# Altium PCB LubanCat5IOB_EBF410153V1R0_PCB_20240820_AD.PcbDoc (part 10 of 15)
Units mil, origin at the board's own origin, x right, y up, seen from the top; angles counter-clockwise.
Board outline 6811.02 x 4055.12 mil, 6 copper layers (TOP, GND02, ART03, ART04, PWR05, BOTTOM), stack 59.279 mil thick; 981 components, 783 nets, 3627 pads, 2669 vias.
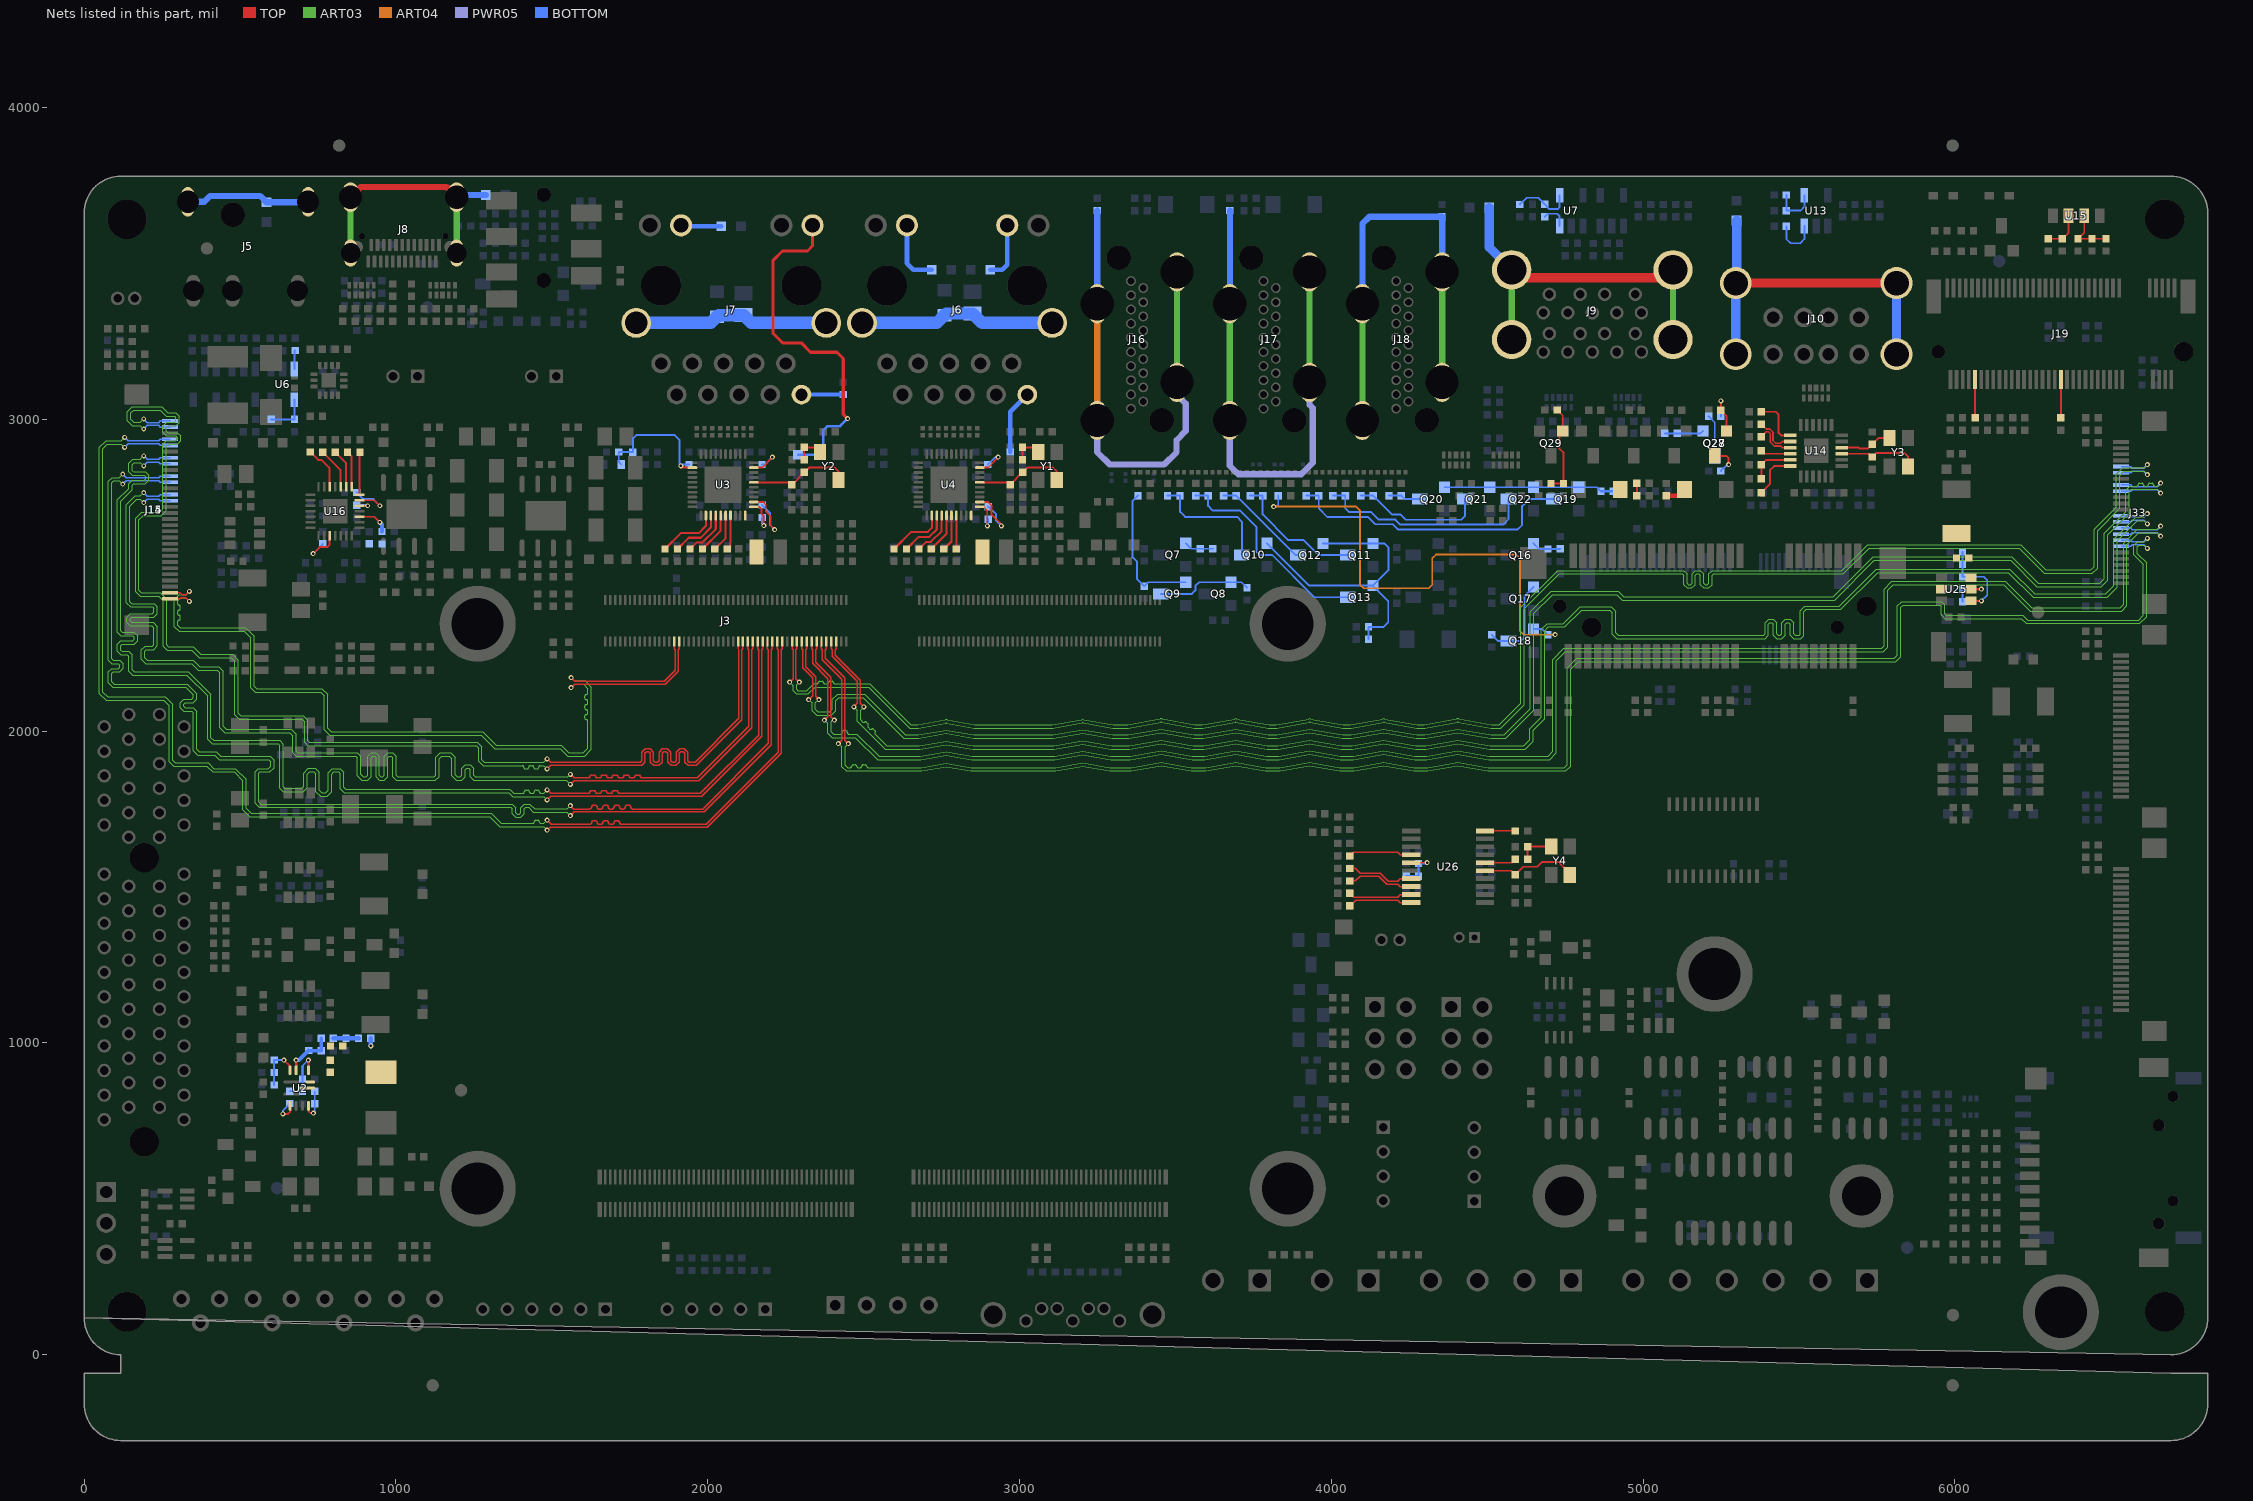
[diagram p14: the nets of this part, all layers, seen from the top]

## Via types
v1: diameter 16, hole 8, TOP to BOTTOM, 2357 vias
v2: diameter 14, hole 8, TOP to BOTTOM, 308 vias
v3: diameter 20, hole 10, TOP to BOTTOM, 4 vias

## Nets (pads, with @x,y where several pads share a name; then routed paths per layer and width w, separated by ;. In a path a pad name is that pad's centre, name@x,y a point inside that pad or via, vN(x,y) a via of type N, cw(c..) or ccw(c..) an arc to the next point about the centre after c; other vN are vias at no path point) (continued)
MIPI_DPHY0_TX_D3N: J3.31 J14.30 | length 2615.6
  TOP w4.5: J14.30@275.91,2424.15 307.43,2424.15 310.52,2427.25 326.5,2427.25 v1(337.83,2415.92) ; v1(1562,2139.17) 1573.33,2150.5 1864.5,2150.5 1905.25,2191.25 1905.25,2260.7 1908.37,2263.82 J3.31@1908.37,2286.88
  ART03 w4: v1(337.83,2415.92) 327.25,2426.5 309,2426.5 300,2417.5 300,2408.5 ccw(c304.5,2408.5) 304.5,2404 cw(c304.5,2399.5) 309,2399.5 309,2392.5 cw(c304.5,2392.5) 304.5,2388 ccw(c304.5,2383.5) 300,2383.5 300,2376.5 ccw(c304.5,2376.5) 304.5,2372 cw(c304.5,2367.5) 309,2367.5 309,2360.5 cw(c304.5,2360.5) 304.5,2356 ccw(c304.5,2351.5) 300,2351.5 300,2340 309,2331 518,2331 545.05,2303.95 545.05,2144 553.05,2136 763,2136 781.27,2117.73 781.27,2009.29 792.56,1998 1278,1998 1322,1954 1531,1954 1555,1930 1600.44,1930 1616,1945.56 1616,2031.61 ccw(c1610.5,2031.61) 1610.5,2037.11 cw(c1610.5,2042.61) 1605,2042.61 1605,2047.61 cw(c1610.5,2047.61) 1610.5,2053.11 ccw(c1610.5,2058.61) 1616,2058.61 1616,2063.61 ccw(c1610.5,2063.61) 1610.5,2069.11 cw(c1610.5,2074.61) 1605,2074.61 1605,2079.61 cw(c1610.5,2079.61) 1610.5,2085.11 ccw(c1610.5,2090.61) 1616,2090.61 1616,2095.61 ccw(c1610.5,2095.61) 1610.5,2101.11 cw(c1610.5,2106.61) 1605,2106.61 1605,2111.61 cw(c1610.5,2111.61) 1610.5,2117.11 ccw(c1610.5,2122.61) 1616,2122.61 1616,2136.44 1602.69,2149.75 1572.58,2149.75 v1(1562,2139.17)
MIPI_DPHY0_TX_D3P: J3.29 J14.29 | length 2616.2
  TOP w4.5: J14.29@275.91,2443.85 307.43,2443.85 314.52,2436.75 326.5,2436.75 v1(337.83,2448.08) ; v1(1562,2171.33) 1573.33,2160 1860.56,2160 1895.75,2195.18 1895.75,2260.7 1892.62,2263.82 J3.29@1892.62,2286.88
  ART03 w4: v1(337.83,2448.08) 327.25,2437.5 304.44,2437.5 289,2422.06 289,2335.44 304.44,2320 513.44,2320 534.05,2299.39 534.05,2139.44 548.49,2125 758.44,2125 770.27,2113.17 770.27,2004.73 788,1987 1273.44,1987 1317.44,1943 1526.44,1943 1550.44,1919 1605,1919 1627,1941 1627,2141 1607.25,2160.75 1572.58,2160.75 v1(1562,2171.33)
MIPI_DPHY1_RX_CLKN: J3.87 J33.10 | length 5558
  TOP w4.5: J3.87@2349.32,2286.88 2349.32,2263.82 2346.19,2260.7 2346.19,2220.81 2395,2172 2395,2046.33 v1(2406.33,2035)
  ART03 w4: v1(2406.33,2035) 2400,2035 2395.75,2030.75 2395.75,1998 2403.75,1990 2425.64,1990 ccw(c2425.64,1996) 2431.64,1996 cw(c2437.64,1996) 2437.64,2002 2441.64,2002 cw(c2441.64,1996) 2447.64,1996 ccw(c2453.64,1996) 2453.64,1990 2478.56,1990 2549.56,1919 2681.91,1919 2765.07,1933.44 2848.24,1919 3112.75,1919 3202.96,1934.66 3293.16,1919 3354.75,1919 3454.61,1936.34 3554.46,1919 3593.75,1919 3693.11,1936.25 3792.46,1919 3831.75,1919 3931.14,1936.26 4030.52,1919 4069.81,1919 4169.1,1936.24 4268.38,1919 4305.75,1919 4406.13,1936.43 4506.5,1919 4695.44,1919 4711,1934.56 4711,2229.56 4746.44,2265 5766,2265 5774,2273 5774,2455.56 5798.44,2480 6162,2480 6245.99,2396.01 6530.45,2396.01 6541,2406.56 6541,2603 6585.15,2647.15 6649.42,2647.15 v1(6660,2657.73)
  BOTTOM w4.5: J33.10@6533.11,2651.49 6564.63,2651.49 6569.73,2646.4 6648.67,2646.4 v1(6660,2657.73)
MIPI_DPHY1_RX_CLKP: J3.85 J33.9 | length 5558.6
  TOP w4.5: J3.85@2333.57,2286.88 2333.57,2263.82 2336.69,2260.7 2336.69,2216.87 2385.5,2168.07 2385.5,2046.33 v1(2374.17,2035)
  ART03 w4: v1(2374.17,2035) 2384.75,2024.42 2384.75,1993.44 2399.19,1979 2474,1979 2545,1908 2682.85,1908 2765.07,1922.28 2847.3,1908 3113.7,1908 3202.96,1923.5 3292.22,1908 3355.7,1908 3454.61,1925.17 3553.51,1908 3594.7,1908 3693.11,1925.09 3791.52,1908 3832.7,1908 3931.14,1925.09 4029.57,1908 4070.76,1908 4169.1,1925.07 4267.43,1908 4306.7,1908 4406.13,1925.26 4505.55,1908 4700,1908 4722,1930 4722,2225 4751,2254 5770.56,2254 5785,2268.44 5785,2451 5803,2469 6157.44,2469 6241.43,2385.01 6535.01,2385.01 6552,2402 6552,2598.44 6589.71,2636.15 6649.42,2636.15 v1(6660,2625.57)
  BOTTOM w4.5: J33.9@6533.11,2631.81 6564.63,2631.81 6569.73,2636.9 6648.67,2636.9 v1(6660,2625.57)
MIPI_DPHY1_RX_D0N: J3.95 J33.12 | length 5560.8
  TOP w4.5: J3.95@2412.31,2286.88 2412.31,2263.82 2409.18,2260.7 2409.18,2243.94 2489.5,2163.62 2489.5,2089.33 v1(2500.83,2078)
  ART03 w4: v1(2500.83,2078) 2490.25,2067.42 2490.25,2036.75 2497.85,2029.15 ccw(c2500.6,2031.9) 2503.35,2029.15 cw(c2506.1,2026.4) 2508.85,2029.15 2514.67,2023.33 cw(c2511.92,2020.58) 2514.67,2017.83 ccw(c2517.42,2015.08) 2514.67,2012.33 2520.48,2006.52 ccw(c2523.23,2009.27) 2525.98,2006.52 cw(c2528.73,2003.77) 2531.48,2006.52 2537.3,2000.7 cw(c2534.55,1997.95) 2537.3,1995.2 ccw(c2540.05,1992.45) 2537.3,1989.7 2574,1953 2678.97,1953 2765.07,1967.95 2851.17,1953 3109.82,1953 3202.96,1969.17 3296.09,1953 3351.82,1953 3454.61,1970.85 3557.39,1953 3590.82,1953 3693.11,1970.76 3795.39,1953 3828.82,1953 3931.14,1970.77 4033.45,1953 4066.88,1953 4169.1,1970.75 4271.31,1953 4302.82,1953 4406.13,1970.94 4509.43,1953 4617.44,1953 4637,1972.56 4637,2007.56 4674,2044.56 4674,2327 4692,2345 4744.44,2345 4798.44,2399 4897.56,2399 4912,2384.56 4912,2315 4920,2307 5386.63,2307 5391.31,2311.69 5391.31,2346.87 5402.44,2358 5418.19,2358 5429.31,2346.87 5429.31,2311.69 5434,2307 5440.63,2307 5445.31,2311.69 5445.31,2346.87 5456.44,2358 5472.19,2358 5483.31,2346.87 5483.31,2311.69 5488,2307 5501,2307 5505,2311 5505,2386.56 5519.44,2401 5629.44,2401 5747.81,2519.37 6176.63,2519.37 6255.63,2440.37 6483.81,2440.37 6510,2466.56 6510,2615.56 6580.44,2686 6606.58,2686 v1(6617.69,2697.1)
  BOTTOM w4.5: J33.12@6533.11,2690.86 6564.63,2690.86 6569.73,2685.77 6606.35,2685.77 v1(6617.69,2697.1)
MIPI_DPHY1_RX_D0P: J3.93 J33.11 | length 5560.6
  TOP w4.5: J3.93@2396.56,2286.88 2396.56,2263.82 2399.68,2260.7 2399.68,2240 2480,2159.68 2480,2089.33 v1(2468.67,2078)
  ART03 w4: v1(2468.67,2078) 2479.25,2067.42 2479.25,2032.19 2569.44,1942 2679.92,1942 2765.07,1956.79 2850.23,1942 3110.77,1942 3202.96,1958.01 3295.15,1942 3352.77,1942 3454.61,1959.68 3556.45,1942 3591.77,1942 3693.11,1959.6 3794.45,1942 3829.77,1942 3931.14,1959.6 4032.5,1942 4067.82,1942 4169.1,1959.58 4270.36,1942 4303.77,1942 4406.13,1959.77 4508.48,1942 4622,1942 4648,1968 4648,2003 4685,2040 4685,2322.44 4696.56,2334 4749,2334 4803,2388 4893,2388 4901,2380 4901,2310.44 4915.44,2296 5391.19,2296 5402.31,2307.13 5402.31,2342.31 5407,2347 5413.63,2347 5418.31,2342.31 5418.31,2307.13 5429.44,2296 5445.19,2296 5456.31,2307.13 5456.31,2342.31 5461,2347 5467.63,2347 5472.31,2342.31 5472.31,2307.13 5483.44,2296 5505.56,2296 5516,2306.44 5516,2382 5524,2390 5634,2390 5752.37,2508.37 6172.07,2508.37 6251.07,2429.37 6488.37,2429.37 6521,2462 6521,2611 6585,2675 6607.63,2675 v1(6617.69,2664.94)
  BOTTOM w4.5: J33.11@6533.11,2671.18 6564.63,2671.18 6569.73,2676.27 6606.35,2676.27 v1(6617.69,2664.94)
MIPI_DPHY1_RX_D1N: J3.91 J33.8 | length 5562.1
  TOP w4.5: J3.91@2380.81,2286.88 2380.81,2263.82 2377.69,2260.7 2377.69,2233.31 2440,2171 2440,1971.33 v1(2451.33,1960)
  ART03 w4: v1(2451.33,1960) 2440.75,1949.42 2440.75,1890.81 2448.56,1883 2457.56,1883 ccw(c2457.56,1887.5) 2462.06,1887.5 cw(c2466.56,1887.5) 2466.56,1892 2473.56,1892 cw(c2473.56,1887.5) 2478.06,1887.5 ccw(c2482.56,1887.5) 2482.56,1883 2489.56,1883 ccw(c2489.56,1887.5) 2494.06,1887.5 cw(c2498.56,1887.5) 2498.56,1892 2505.56,1892 cw(c2505.56,1887.5) 2510.06,1887.5 ccw(c2514.56,1887.5) 2514.56,1883 2685.01,1883 2765.07,1896.9 2845.14,1883 3115.86,1883 3202.96,1898.12 3290.06,1883 3357.86,1883 3454.61,1899.8 3551.36,1883 3596.86,1883 3693.11,1899.71 3789.36,1883 3834.86,1883 3931.14,1899.71 4027.41,1883 4072.91,1883 4169.1,1899.7 4265.28,1883 4308.86,1883 4406.13,1899.89 4503.39,1883 4747.44,1883 4757,1892.56 4757,2203 4788,2234 5806.44,2234 5816,2243.56 5816,2401.56 5829.81,2415.37 5957.56,2415.37 5968,2404.93 5968,2377 5973,2372 6218,2372 6233.73,2356.27 6589.27,2356.27 6604,2371 6604,2535 6574,2565 6574,2595.56 6586.23,2607.78 6607.1,2607.78 v1(6617.69,2618.36)
  BOTTOM w4.5: J33.8@6533.11,2612.12 6564.63,2612.12 6569.73,2607.03 6606.35,2607.03 v1(6617.69,2618.36)
MIPI_DPHY1_RX_D1P: J3.89 J33.7 | length 5559.6
  TOP w4.5: J3.89@2365.06,2286.88 2365.06,2263.82 2368.19,2260.7 2368.19,2229.38 2430.5,2167.06 2430.5,1971.33 v1(2419.17,1960)
  ART03 w4: v1(2419.17,1960) 2429.75,1949.42 2429.75,1886.25 2444,1872 2685.96,1872 2765.07,1885.74 2844.19,1872 3116.8,1872 3202.96,1886.96 3289.11,1872 3358.8,1872 3454.61,1888.63 3550.41,1872 3597.8,1872 3693.11,1888.55 3788.41,1872 3835.8,1872 3931.14,1888.55 4026.47,1872 4073.86,1872 4169.1,1888.53 4264.33,1872 4309.81,1872 4406.13,1888.72 4502.45,1872 4752,1872 4768,1888 4768,2198.44 4792.56,2223 5811,2223 5827,2239 5827,2397 5834.37,2404.37 5953,2404.37 5957,2400.37 5957,2372.44 5968.44,2361 6213.44,2361 6229.17,2345.27 6593.83,2345.27 6615,2366.44 6615,2539.56 6585,2569.56 6585,2591 6590.78,2596.78 6607.1,2596.78 v1(6617.69,2586.2)
  BOTTOM w4.5: J33.7@6533.11,2592.44 6564.63,2592.44 6569.73,2597.53 6606.35,2597.53 v1(6617.69,2586.2)
MIPI_DPHY1_RX_D2N: J3.83 J33.17 | length 5556.2
  TOP w4.5: J3.83@2317.82,2286.88 2317.82,2263.83 2314.7,2260.7 2314.7,2206.3 2346,2175 2346,2111.44 v1(2356.33,2101.11)
  ART03 w4: v1(2356.33,2101.11) 2345.75,2090.52 2345.75,2070 2353.75,2062 2392.2,2062 2400.2,2070 2400.2,2101.76 2416.44,2118 2504,2118 2634,1988 2675.96,1988 2765.07,2003.47 2854.19,1988 3106.81,1988 3202.96,2004.7 3299.11,1988 3348.81,1988 3454.61,2006.37 3560.41,1988 3587.81,1988 3693.11,2006.29 3798.41,1988 3825.81,1988 3931.14,2006.29 4036.46,1988 4063.86,1988 4169.1,2006.27 4274.33,1988 4299.81,1988 4406.13,2006.46 4512.44,1988 4555.44,1988 4639,2071.56 4639,2382.56 4705.44,2449 4920,2449 4938,2431 5610,2431 5737.74,2558.74 6183.19,2558.74 6267.56,2474.37 6464.81,2474.37 6479,2488.56 6479,2634 6548,2703 6548,2772.56 6561.36,2785.92 6584.15,2785.92 ccw(c6584.15,2790.46) 6588.69,2790.46 cw(c6593.23,2790.46) 6593.23,2795 6600.15,2795 cw(c6600.15,2790.46) 6604.69,2790.46 ccw(c6609.23,2790.46) 6609.23,2785.92 6616.15,2785.92 ccw(c6616.15,2790.46) 6620.69,2790.46 cw(c6625.23,2790.46) 6625.23,2795 6632.15,2795 cw(c6632.15,2790.46) 6636.69,2790.46 ccw(c6641.23,2790.46) 6641.23,2785.92 6650.39,2785.92 v1(6660,2795.53)
  BOTTOM w4.5: J33.17@6533.11,2789.29 6564.63,2789.29 6569.73,2784.2 6648.67,2784.2 v1(6660,2795.53)
MIPI_DPHY1_RX_D2P: J3.81 J33.16 | length 5555.1
  TOP w4.5: J3.81@2302.07,2286.88 2302.07,2263.82 2305.2,2260.7 2305.2,2202.37 2336.5,2171.06 2336.5,2113.43 v1(2324.17,2101.11)
  ART03 w4: v1(2324.17,2101.11) 2334.75,2090.53 2334.75,2065.44 2349.19,2051 2396.76,2051 2411.2,2065.44 2411.2,2097.2 2421,2107 2499.44,2107 2629.44,1977 2676.91,1977 2765.07,1992.31 2853.24,1977 3107.75,1977 3202.96,1993.53 3298.16,1977 3349.75,1977 3454.61,1995.21 3559.46,1977 3588.75,1977 3693.11,1995.12 3797.46,1977 3826.76,1977 3931.14,1995.12 4035.51,1977 4064.81,1977 4169.1,1995.11 4273.38,1977 4300.76,1977 4406.13,1995.3 4511.5,1977 4560,1977 4650,2067 4650,2378 4710,2438 4915.44,2438 4933.44,2420 5614.56,2420 5742.3,2547.74 6178.63,2547.74 6263,2463.37 6469.37,2463.37 6490,2484 6490,2629.44 6559,2698.44 6559,2768 6565.92,2774.92 6648.45,2774.92 v1(6660,2763.37)
  BOTTOM w4.5: J33.16@6533.11,2769.61 6564.63,2769.61 6569.73,2774.7 6648.67,2774.7 v1(6660,2763.37)
MIPI_DPHY1_RX_D3N: J3.79 J33.20 | length 5558.8
  TOP w4.5: J3.79@2286.32,2286.88 2286.32,2263.82 2283.2,2260.7 2283.2,2167.44 v1(2293.79,2156.85)
  ART03 w4: v1(2293.79,2156.85) 2285,2148.06 2285,2134 2289,2130 2318.44,2130 2340.44,2152 2351.43,2152 ccw(c2351.43,2156) 2355.43,2156 cw(c2359.43,2156) 2359.43,2160 2367.43,2160 cw(c2367.43,2156) 2371.43,2156 ccw(c2375.43,2156) 2375.43,2152 2383.43,2152 ccw(c2383.43,2156) 2387.43,2156 cw(c2391.43,2156) 2391.43,2160 2399.43,2160 cw(c2399.43,2156) 2403.43,2156 ccw(c2407.43,2156) 2407.43,2152 2520.56,2152 2652.06,2020.5 2672.46,2020.5 ccw(c2672.46,2028.5) 2673.83,2020.62 2761.82,2035.9 cw(c2765.07,2017.18) 2768.33,2035.9 2856.32,2020.62 ccw(c2857.69,2028.5) 2857.69,2020.5 3103.31,2020.5 ccw(c3103.31,2028.5) 3104.68,2020.62 3199.71,2037.12 cw(c3202.96,2018.4) 3206.21,2037.12 3301.24,2020.62 ccw(c3302.61,2028.5) 3302.61,2020.5 3345.31,2020.5 ccw(c3345.31,2028.5) 3346.68,2020.62 3451.36,2038.79 cw(c3454.61,2020.07) 3457.86,2038.79 3562.54,2020.62 ccw(c3563.91,2028.5) 3563.91,2020.5 3584.31,2020.5 ccw(c3584.31,2028.5) 3585.68,2020.62 3689.86,2038.71 cw(c3693.11,2019.99) 3696.36,2038.71 3800.54,2020.62 ccw(c3801.91,2028.5) 3801.91,2020.5 3822.31,2020.5 ccw(c3822.31,2028.5) 3823.68,2020.62 3927.89,2038.71 cw(c3931.14,2019.99) 3934.39,2038.71 4038.59,2020.62 ccw(c4039.96,2028.5) 4039.96,2020.5 4060.36,2020.5 ccw(c4060.36,2028.5) 4061.73,2020.62 4165.84,2038.69 cw(c4169.1,2019.97) 4172.35,2038.69 4276.46,2020.62 ccw(c4277.83,2028.5) 4277.83,2020.5 4296.31,2020.5 ccw(c4296.31,2028.5) 4297.68,2020.62 4402.88,2038.88 cw(c4406.13,2020.16) 4409.38,2038.88 4514.57,2020.62 ccw(c4515.94,2028.5) 4515.94,2020.5 4538.94,2020.5 4608,2089.56 4608,2396.56 4726.44,2515 5129.97,2515 5141.1,2503.87 5141.1,2474.69 5145.78,2470 5152.41,2470 5157.1,2474.69 5157.1,2503.87 5168.23,2515 5183.97,2515 5195.1,2503.87 5195.1,2474.69 5199.78,2470 5206.41,2470 5211.1,2474.69 5211.1,2503.87 5222.23,2515 5638,2515 5721.11,2598.11 6210.82,2598.11 6291.93,2517 6436.44,2517 6447,2527.56 6447,2647.56 6518,2718.56 6518,2824.08 6537.93,2844 6607.1,2844 v1(6617.69,2854.58)
  BOTTOM w4.5: J33.20@6533.11,2848.35 6564.63,2848.35 6569.73,2843.25 6606.35,2843.25 v1(6617.69,2854.58)
MIPI_DPHY1_RX_D3P: J3.77 J33.19 | length 5559.6
  TOP w4.5: v1(2263.11,2156.85) 2273.7,2167.44 2273.7,2260.7 2270.57,2263.82 J3.77@2270.57,2286.88
  ART03 w4: v1(2263.11,2156.85) 2274,2145.96 2274,2129.44 2284.44,2119 2323,2119 2345,2141 2516,2141 2647.5,2009.5 2672.46,2009.5 ccw(c2672.46,2028.5) 2675.71,2009.78 2763.71,2025.06 cw(c2765.07,2017.18) 2766.44,2025.06 2854.44,2009.78 ccw(c2857.69,2028.5) 2857.69,2009.5 3103.31,2009.5 ccw(c3103.31,2028.5) 3106.56,2009.78 3201.59,2026.28 cw(c3202.96,2018.4) 3204.33,2026.28 3299.36,2009.78 ccw(c3302.61,2028.5) 3302.61,2009.5 3345.31,2009.5 ccw(c3345.31,2028.5) 3348.56,2009.78 3453.24,2027.96 cw(c3454.61,2020.07) 3455.98,2027.96 3560.66,2009.78 ccw(c3563.91,2028.5) 3563.91,2009.5 3584.31,2009.5 ccw(c3584.31,2028.5) 3587.56,2009.78 3691.74,2027.87 cw(c3693.11,2019.99) 3694.48,2027.87 3798.66,2009.78 ccw(c3801.91,2028.5) 3801.91,2009.5 3822.31,2009.5 ccw(c3822.31,2028.5) 3825.56,2009.78 3929.77,2027.87 cw(c3931.14,2019.99) 3932.5,2027.87 4036.71,2009.78 ccw(c4039.96,2028.5) 4039.96,2009.5 4060.36,2009.5 ccw(c4060.36,2028.5) 4063.61,2009.78 4167.73,2027.86 cw(c4169.1,2019.97) 4170.46,2027.86 4274.58,2009.78 ccw(c4277.83,2028.5) 4277.83,2009.5 4296.31,2009.5 ccw(c4296.31,2028.5) 4299.56,2009.78 4404.76,2028.05 cw(c4406.13,2020.16) 4407.49,2028.05 4512.69,2009.78 ccw(c4515.94,2028.5) 4515.94,2009.5 4543.5,2009.5 4619,2085 4619,2392 4731,2504 5125.41,2504 5130.1,2499.31 5130.1,2470.13 5141.23,2459 5156.97,2459 5168.1,2470.13 5168.1,2499.31 5172.78,2504 5179.41,2504 5184.1,2499.31 5184.1,2470.13 5195.23,2459 5210.97,2459 5222.1,2470.13 5222.1,2499.31 5226.78,2504 5642.56,2504 5725.67,2587.11 6206.26,2587.11 6287.37,2506 6441,2506 6458,2523 6458,2643 6529,2714 6529,2819.52 6542.48,2833 6607.1,2833 v1(6617.69,2822.42)
  BOTTOM w4.5: J33.19@6533.11,2828.66 6564.63,2828.66 6569.73,2833.75 6606.35,2833.75 v1(6617.69,2822.42)
MIPI_DPHY1_TX_CLKN: J3.65 J15.24 | length 4024.9
  TOP w4.5: v1(1485,1779.17) 1496.33,1790.5 1980.5,1790.5 2172.96,1982.96 2172.96,2260.7 2176.09,2263.82 J3.65@2176.09,2286.88
  ART03 w4: v1(191.33,2882.94) 180.75,2872.36 156.44,2872.36 143,2858.93 143,2831.22 154.13,2820.1 192.31,2820.1 197,2815.41 197,2808.78 192.31,2804.1 154.13,2804.1 143,2792.97 143,2777.93 107,2741.93 107,2316.59 118.13,2305.46 155.92,2305.46 160.61,2300.77 160.61,2294.14 155.92,2289.46 118.13,2289.46 107,2278.33 107,2255.51 118.13,2244.39 138.31,2244.39 143,2239.7 143,2192.44 156.44,2179 330,2179 395.94,2113.06 395.94,1974.5 411.44,1959 622.44,1959 628,1953.44 628,1817.44 639.44,1806 703,1806 715.37,1818.37 715.37,1860.8 723.94,1869.37 737.07,1869.37 743.74,1862.7 743.74,1805.27 758.38,1790.63 779.1,1790.63 793.74,1805.27 793.74,1861.74 801,1869 816.44,1869 822.11,1863.33 822.11,1814.89 834.37,1802.63 1361.37,1802.63 1374.25,1789.75 1474.42,1789.75 v1(1485,1779.17)
  BOTTOM w4.5: v1(191.33,2882.94) 202.66,2871.61 239.29,2871.61 244.38,2876.71 J15.24@275.91,2876.71
MIPI_DPHY1_TX_CLKP: J3.63 J15.23 | length 4027
  TOP w4.5: v1(1485,1811.33) 1496.33,1800 1617.87,1800 ccw(c1617.87,1804.5) 1622.37,1804.5 cw(c1626.87,1804.5) 1626.87,1809 1635.87,1809 cw(c1635.87,1804.5) 1640.37,1804.5 ccw(c1644.87,1804.5) 1644.87,1800 1653.87,1800 ccw(c1653.87,1804.5) 1658.37,1804.5 cw(c1662.87,1804.5) 1662.87,1809 1671.87,1809 cw(c1671.87,1804.5) 1676.37,1804.5 ccw(c1680.87,1804.5) 1680.87,1800 1689.87,1800 ccw(c1689.87,1804.5) 1694.37,1804.5 cw(c1698.87,1804.5) 1698.87,1809 1707.87,1809 cw(c1707.87,1804.5) 1712.37,1804.5 ccw(c1716.87,1804.5) 1716.87,1800 1976.56,1800 2163.46,1986.9 2163.46,2260.7 2160.34,2263.82 J3.63@2160.34,2286.88
  ART03 w4: v1(191.33,2850.78) 180.75,2861.36 160.99,2861.36 154,2854.37 154,2835.78 158.69,2831.1 196.87,2831.1 208,2819.97 208,2804.22 196.87,2793.1 158.69,2793.1 154,2788.41 154,2773.37 118,2737.37 118,2321.14 122.69,2316.46 160.48,2316.46 171.61,2305.33 171.61,2289.59 160.48,2278.46 122.69,2278.46 118,2273.77 118,2260.07 122.69,2255.39 142.87,2255.39 154,2244.26 154,2197 161,2190 334.56,2190 406.94,2117.62 406.94,1979.06 416,1970 627,1970 639,1958 639,1822 644,1817 698.44,1817 704.37,1822.93 704.37,1865.36 719.38,1880.37 741.63,1880.37 754.74,1867.26 754.74,1809.83 762.94,1801.63 774.54,1801.63 782.74,1809.83 782.74,1866.3 796.44,1880 821,1880 833.11,1867.89 833.11,1819.45 838.93,1813.63 1365.93,1813.63 1378.81,1800.75 1407.17,1800.75 ccw(c1407.17,1805.88) 1412.29,1805.88 cw(c1417.42,1805.88) 1417.42,1811 1423.17,1811 cw(c1423.17,1805.88) 1428.29,1805.88 ccw(c1433.42,1805.88) 1433.42,1800.75 1439.17,1800.75 ccw(c1439.17,1805.88) 1444.29,1805.88 cw(c1449.42,1805.88) 1449.42,1811 1455.17,1811 cw(c1455.17,1805.88) 1460.29,1805.88 ccw(c1465.42,1805.88) 1465.42,1800.75 1474.42,1800.75 v1(1485,1811.33)
  BOTTOM w4.5: v1(191.33,2850.78) 202.66,2862.11 239.29,2862.11 244.38,2857.02 J15.23@275.91,2857.02
MIPI_DPHY1_TX_D0N: J3.73 J15.27 | length 4026.6
  TOP w4.5: v1(1485,1682.18) 1494.36,1691.55 1998.98,1691.55 2235.95,1928.52 2235.95,2260.7 2239.08,2263.82 J3.73@2239.08,2286.88
  ART03 w4: v1(130,2942) 119.42,2931.42 70.44,2931.42 49,2909.97 49,2120.44 71.07,2098.37 256.07,2098.37 273,2081.44 273,1901.44 287.44,1887 394,1887 412,1869 481,1869 509,1841 509,1748 532,1725 1301,1725 1333.23,1692.77 1474.42,1692.77 v1(1485,1682.18)
  BOTTOM w4.5: v1(130,2942) 141.33,2930.67 239.29,2930.67 244.38,2935.76 J15.27@275.91,2935.76
MIPI_DPHY1_TX_D0P: J3.71 J15.26 | length 4025.2
  TOP w4.5: v1(1485,1714.35) 1498.3,1701.05 1622.27,1701.05 ccw(c1622.27,1706.52) 1627.75,1706.52 cw(c1633.22,1706.52) 1633.22,1712 1640.27,1712 cw(c1640.27,1706.52) 1645.75,1706.52 ccw(c1651.22,1706.52) 1651.22,1701.05 1658.27,1701.05 ccw(c1658.27,1706.52) 1663.75,1706.52 cw(c1669.22,1706.52) 1669.22,1712 1676.27,1712 cw(c1676.27,1706.52) 1681.75,1706.52 ccw(c1687.22,1706.52) 1687.22,1701.05 1694.27,1701.05 ccw(c1694.27,1706.52) 1699.75,1706.52 cw(c1705.22,1706.52) 1705.22,1712 1712.27,1712 cw(c1712.27,1706.52) 1717.75,1706.52 ccw(c1723.22,1706.52) 1723.22,1701.05 1995.05,1701.05 2226.45,1932.45 2226.45,2260.7 2223.33,2263.82 J3.71@2223.33,2286.88
  ART03 w4: v1(130,2909.84) 119.42,2920.42 75,2920.42 60,2905.42 60,2125 75.63,2109.37 260.63,2109.37 284,2086 284,1906 292,1898 398.56,1898 416.56,1880 485.56,1880 520,1845.56 520,1752.56 536.56,1736 1305.56,1736 1337.79,1703.77 1439.18,1703.77 ccw(c1439.18,1708.88) 1444.3,1708.88 cw(c1449.42,1708.88) 1449.42,1714 1455.18,1714 cw(c1455.18,1708.88) 1460.3,1708.88 ccw(c1465.42,1708.88) 1465.42,1703.77 1474.42,1703.77 v1(1485,1714.35)
  BOTTOM w4.5: v1(130,2909.84) 141.33,2921.17 239.29,2921.17 244.38,2916.08 J15.26@275.91,2916.08
MIPI_DPHY1_TX_D1N: J3.69 J15.21 | length 4023.9
  TOP w4.5: v1(1560,1728.68) 1571.82,1740.5 1988.5,1740.5 2204.46,1956.46 2204.46,2260.7 2207.58,2263.82 J3.69@2207.58,2286.88
  ART03 w4: v1(124,2823.89) 113.42,2813.31 89.94,2813.31 78,2801.37 78,2227.83 89.13,2216.7 109.31,2216.7 114,2212.01 114,2205.39 109.31,2200.7 89.13,2200.7 78,2189.57 78,2154.44 92.44,2140 326,2140 350,2116 350,2107 345.31,2102.31 320.13,2102.31 309,2091.18 309,2075.44 320.13,2064.31 345.31,2064.31 350,2059.63 350,1937.44 364.44,1923 419,1923 433.63,1908.37 592.07,1908.37 598.37,1902.07 598.37,1886.93 591.44,1880 559.3,1880 548.86,1869.56 548.86,1768.59 562.44,1755 1369.07,1755 1373.76,1750.31 1373.76,1734.13 1384.89,1723 1400.63,1723 1411.76,1734.13 1411.76,1750.31 1416.44,1755 1425.44,1755 1440.44,1740 1548.68,1740 v1(1560,1728.68)
  BOTTOM w4.5: v1(124,2823.89) 135.33,2812.56 239.29,2812.56 244.38,2817.65 J15.21@275.91,2817.65
MIPI_DPHY1_TX_D1P: J3.67 J15.20 | length 4025.5
  TOP w4.5: v1(1560,1760.84) 1570.84,1750 1621.54,1750 ccw(c1621.54,1756) 1627.54,1756 cw(c1633.54,1756) 1633.54,1762 1639.54,1762 cw(c1639.54,1756) 1645.54,1756 ccw(c1651.54,1756) 1651.54,1750 1657.54,1750 ccw(c1657.54,1756) 1663.54,1756 cw(c1669.54,1756) 1669.54,1762 1675.54,1762 cw(c1675.54,1756) 1681.54,1756 ccw(c1687.54,1756) 1687.54,1750 1693.54,1750 ccw(c1693.54,1756) 1699.54,1756 cw(c1705.54,1756) 1705.54,1762 1711.54,1762 cw(c1711.54,1756) 1717.54,1756 ccw(c1723.54,1756) 1723.54,1750 1729.54,1750 ccw(c1729.54,1756) 1735.54,1756 cw(c1741.54,1756) 1741.54,1762 1747.54,1762 cw(c1747.54,1756) 1753.54,1756 ccw(c1759.54,1756) 1759.54,1750 1984.56,1750 2194.96,1960.39 2194.96,2260.7 2191.84,2263.82 J3.67@2191.84,2286.88
  ART03 w4: v1(124,2791.73) 113.42,2802.31 94.5,2802.31 89,2796.81 89,2232.39 93.69,2227.7 113.87,2227.7 125,2216.57 125,2200.83 113.87,2189.7 93.69,2189.7 89,2185.01 89,2159 97,2151 330.56,2151 361,2120.56 361,2102.44 349.87,2091.31 324.69,2091.31 320,2086.63 320,2080 324.69,2075.31 349.87,2075.31 361,2064.18 361,1942 369,1934 423.56,1934 438.19,1919.37 596.63,1919.37 609.37,1906.63 609.37,1882.37 596,1869 563.86,1869 559.86,1865 559.86,1773.14 567,1766 1373.63,1766 1384.76,1754.87 1384.76,1738.69 1389.44,1734 1396.07,1734 1400.76,1738.69 1400.76,1754.87 1411.89,1766 1430,1766 1445,1751 1550.16,1751 v1(1560,1760.84)
  BOTTOM w4.5: v1(124,2791.73) 135.33,2803.06 239.29,2803.06 244.38,2797.97 J15.20@275.91,2797.97
MIPI_DPHY1_TX_D2N: J3.61 J15.18 | length 4025.9
  TOP w4.5: v1(1560,1829.17) 1571.33,1840.5 1970.94,1840.5 2141.47,2011.03 2141.47,2260.7 2144.59,2263.82 J3.61@2144.59,2286.88
  ART03 w4: v1(191.33,2764.83) 180.75,2754.25 164.88,2754.25 136,2725.38 136,2411 149,2398 220,2398 224,2394 224,2380.44 219.31,2375.76 148.13,2375.76 137,2364.63 137,2348.89 148.13,2337.76 216.69,2337.76 224,2330.44 224,2277.56 218.44,2272 195.44,2272 183.61,2260.16 183.61,2230.84 198.44,2216 345.44,2216 366.02,2195.42 426.74,2195.42 435.31,2186.85 435.31,2011.13 451.44,1995 659.44,1995 669,1985.44 669,1930.44 680.44,1919 871.44,1919 876,1914.44 876,1856.44 890.44,1842 909.11,1842 920.24,1853.13 920.24,1914.31 924.93,1919 931.56,1919 936.24,1914.31 936.24,1853.13 947.37,1842 963.11,1842 974.24,1853.13 974.24,1914.31 978.93,1919 985.56,1919 990.24,1914.31 990.24,1853.13 1001.37,1842 1127,1842 1139,1854 1139,1911.44 1146.56,1919 1171.44,1919 1179,1911.44 1179,1856 1193,1842 1211.11,1842 1222.24,1853.13 1222.24,1876.31 1226.93,1881 1233.56,1881 1238.24,1876.31 1238.24,1853.13 1249.37,1842 1547.17,1842 v1(1560,1829.17)
  BOTTOM w4.5: v1(191.33,2764.83) 202.66,2753.5 239.29,2753.5 244.38,2758.6 J15.18@275.91,2758.6
MIPI_DPHY1_TX_D2P: J3.59 J15.17 | length 4023.3
  TOP w4.5: v1(1560,1861.33) 1571.33,1850 1617.99,1850 ccw(c1617.99,1854.5) 1622.49,1854.5 cw(c1626.99,1854.5) 1626.99,1859 1635.99,1859 cw(c1635.99,1854.5) 1640.49,1854.5 ccw(c1644.99,1854.5) 1644.99,1850 1653.99,1850 ccw(c1653.99,1854.5) 1658.49,1854.5 cw(c1662.99,1854.5) 1662.99,1859 1671.99,1859 cw(c1671.99,1854.5) 1676.49,1854.5 ccw(c1680.99,1854.5) 1680.99,1850 1689.99,1850 ccw(c1689.99,1854.5) 1694.49,1854.5 cw(c1698.99,1854.5) 1698.99,1859 1707.99,1859 cw(c1707.99,1854.5) 1712.49,1854.5 ccw(c1716.99,1854.5) 1716.99,1850 1725.99,1850 ccw(c1725.99,1854.5) 1730.49,1854.5 cw(c1734.99,1854.5) 1734.99,1859 1743.99,1859 cw(c1743.99,1854.5) 1748.49,1854.5 ccw(c1752.99,1854.5) 1752.99,1850 1761.99,1850 ccw(c1761.99,1854.5) 1766.49,1854.5 cw(c1770.99,1854.5) 1770.99,1859 1779.99,1859 cw(c1779.99,1854.5) 1784.49,1854.5 ccw(c1788.99,1854.5) 1788.99,1850 1967,1850 2131.97,2014.97 2131.97,2260.7 2128.84,2263.82 J3.59@2128.84,2286.88
  ART03 w4: v1(191.33,2732.67) 180.75,2743.25 169.43,2743.25 147,2720.82 147,2415.56 153.56,2409 224.56,2409 235,2398.56 235,2375.89 223.87,2364.76 152.69,2364.76 148,2360.07 148,2353.44 152.69,2348.76 221.24,2348.76 235,2335 235,2273 223,2261 200,2261 194.61,2255.61 194.61,2235.39 203,2227 350,2227 370.58,2206.42 431.3,2206.42 446.31,2191.41 446.31,2015.69 456,2006 664,2006 680,1990 680,1935 685,1930 876,1930 887,1919 887,1861 895,1853 904.56,1853 909.24,1857.69 909.24,1918.87 920.37,1930 936.11,1930 947.24,1918.87 947.24,1857.69 951.93,1853 958.56,1853 963.24,1857.69 963.24,1918.87 974.37,1930 990.11,1930 1001.24,1918.87 1001.24,1857.69 1005.93,1853 1122.44,1853 1128,1858.56 1128,1916 1142,1930 1176,1930 1190,1916 1190,1860.56 1197.56,1853 1206.56,1853 1211.24,1857.69 1211.24,1880.87 1222.37,1892 1238.11,1892 1249.24,1880.87 1249.24,1857.69 1253.93,1853 1551.67,1853 v1(1560,1861.33)
  BOTTOM w4.5: v1(191.33,2732.67) 202.66,2744 239.29,2744 244.38,2738.91 J15.17@275.91,2738.91
MIPI_DPHY1_TX_D3N: J3.57 J15.30 | length 4029.4
  TOP w4.5: v1(1485,1878.67) 1496.33,1890 1787.78,1890 1798.62,1900.84 1798.62,1928.23 1803.89,1933.5 1811.35,1933.5 1816.62,1928.23 1816.62,1900.84 1827.45,1890 1842.78,1890 1853.62,1900.84 1853.62,1928.23 1858.89,1933.5 1866.35,1933.5 1871.62,1928.23 1871.62,1900.84 1882.45,1890 1897.78,1890 1908.62,1900.84 1908.62,1928.23 1913.89,1933.5 1921.35,1933.5 1926.62,1928.23 1926.62,1900.84 1937.45,1890 1963.43,1890 2109.97,2036.54 2109.97,2260.7 2113.09,2263.82 J3.57@2113.09,2286.88
  ART03 w4: v1(191.33,3001.05) 180.75,2990.47 159,2990.47 150,2999.47 150,3020.37 159,3029.37 244,3029.37 263.37,3010 290,3010 294,3006 294,2994 290,2990 265,2990 252,2977 252,2957.76 263.13,2946.63 294.31,2946.63 299,2941.94 299,2935.31 294.31,2930.63 263.13,2930.63 252,2919.5 252,2711.56 242.81,2702.37 184.44,2702.37 165,2682.93 165,2447.44 179.44,2433 239,2433 254,2418 254,2272 266,2260 345,2260 370,2235 471.44,2235 483,2223.44 483,2052.75 497.44,2038.31 699,2038.31 707,2030.31 707,1964 718,1953 1257,1953 1265,1945 1265,1903.69 1279.44,1889.25 1404.92,1889.25 cw(c1404.92,1884.13) 1410.05,1884.13 ; 1410.05,1884.12 ccw(c1415.17,1884.12) 1415.17,1879 1420.92,1879 ccw(c1420.92,1884.12) 1426.05,1884.12 ; 1426.05,1884.13 cw(c1431.17,1884.13) 1431.17,1889.25 1436.92,1889.25 cw(c1436.92,1884.13) 1442.05,1884.13 ; 1442.05,1884.12 ccw(c1447.17,1884.12) 1447.17,1879 1452.92,1879 ccw(c1452.92,1884.12) 1458.05,1884.12 ; 1458.05,1884.13 cw(c1463.17,1884.13) 1463.17,1889.25 1474.42,1889.25 v1(1485,1878.67)
  BOTTOM w4.5: v1(191.33,3001.05) 202.66,2989.72 239.29,2989.72 244.38,2994.82 J15.30@275.91,2994.82
MIPI_DPHY1_TX_D3P: J3.55 J15.29 | length 4026.7
  TOP w4.5: v1(1485,1910.83) 1496.33,1899.5 1783.85,1899.5 1789.12,1904.77 1789.12,1932.16 1799.95,1943 1815.28,1943 1826.12,1932.16 1826.12,1904.77 1831.39,1899.5 1838.85,1899.5 1844.12,1904.77 1844.12,1932.16 1854.95,1943 1870.28,1943 1881.12,1932.16 1881.12,1904.77 1886.39,1899.5 1893.85,1899.5 1899.12,1904.77 1899.12,1932.16 1909.95,1943 1925.28,1943 1936.12,1932.16 1936.12,1904.77 1941.39,1899.5 1959.5,1899.5 2100.47,2040.47 2100.47,2260.7 2097.35,2263.82 J3.55@2097.35,2286.88
  ART03 w4: v1(191.33,2968.89) 180.75,2979.47 154.44,2979.47 139,2994.91 139,3024.93 154.44,3040.37 248.56,3040.37 267.93,3021 294.56,3021 305,3010.56 305,2989.44 294.56,2979 269.56,2979 263,2972.44 263,2962.31 267.69,2957.63 298.87,2957.63 310,2946.5 310,2930.76 298.87,2919.63 267.69,2919.63 263,2914.94 263,2707 247.37,2691.37 189,2691.37 176,2678.37 176,2452 184,2444 243.56,2444 265,2422.56 265,2276.56 270.56,2271 349.56,2271 374.56,2246 476,2246 494,2228 494,2057.31 502,2049.31 703.56,2049.31 718,2034.87 718,1968.56 722.56,1964 1261.56,1964 1276,1949.56 1276,1908.25 1284,1900.25 1474.42,1900.25 v1(1485,1910.83)
  BOTTOM w4.5: v1(191.33,2968.89) 202.66,2980.22 239.29,2980.22 244.38,2975.12 J15.29@275.91,2975.12
N16593687: C16.1 R8.2
N16593695: C16.2 L3.1 R10.1 U2.7 | length 25
  BOTTOM w15: v1(919.68,990) R10.1@919.68,1015
N16593775: C20.1 R10.2 R13.2 | length 80.9
  BOTTOM w15: R13.2@799.68,1015.04 839.68,1015.04 C20.1@840,1014.72 880.04,1014.72 R10.2@880.32,1015
N16593791: R12.2 R13.1 R17.1 U2.11 | length 165.8
  TOP w8: U2.11@680.16,912.13 v1(680.16,945.04)
  BOTTOM w6: R17.1@720,975.36 R17.1@720.32,975.04
  BOTTOM w12: v1(680.16,945.04) 689.68,945.04 R17.1@720,975.36 ; R17.1@720.32,975.04 R12.2@760.32,975.04 R13.1@760.32,1015.04
N16594273: J5.1 J5.5 L1.1 | length 402.8
  BOTTOM w20: J5.1@332.67,3697.67 385.3,3697.67 404,3716.37 564.5,3716.37 L1.1@585,3695.87 716.67,3695.87 J5.5@718.47,3697.67
N16594503: C26.1 R9.2 R16.1 U2.12 | length 152.2
  TOP w6: v1(640.79,945.04) 660.47,925.36 U2.12@660.47,912.13
  BOTTOM w6: C26.1@609.68,865.04 R16.1@609.68,905.04 R9.2@609.68,945.04 v1(640.79,945.04)
N16594633: R15.2 U2.3 | length 86.9
  TOP w6: v1(637.48,772.38) 653.67,772.38 660.47,779.18 U2.3@660.47,797.95
  BOTTOM w6: v1(637.48,772.38) 637.48,782.84 R15.2@660,805.36
N16594645: R14.2 R18.1 U2.6 | length 107.7
  TOP w6: U2.6@719.53,797.95 719.53,781.17 726.33,774.37 v1(735,774.37)
  BOTTOM w6: v1(735,774.37) 739.68,779.05 R18.1@739.68,805.04 R14.2@739.68,845.04
N16594663: C25.1 R14.1 R15.1 U2.9 | length 181.3
  TOP w6: U2.9@719.53,912.13 v1(719.53,945.04)
  BOTTOM w6: R15.1@660,844.72 660.32,845.04 R14.1@700.32,845.04 C25.1@700.32,884.37 700.32,925.83 v1(719.53,945.04)
N16594691: R8.1 U2.8
N16605614: C36.1 J6.15 J6.16 R42.1 | length 634.9
  BOTTOM w40: J6.16@2495.08,3309.06 2734.69,3309.06 R42.1@2760,3334.37 2764.96,3339.33 C36.1@2850,3339.33 2880.27,3309.06 J6.15@3104.92,3309.06
N16605678: J6.13 R39.1 | length 209.8
  BOTTOM w15: J6.13@2639.17,3622.06 2639.17,3500.2 2660,3479.37 R39.1@2718.5,3479.37
N16605786: R45.1 U4.32 | length 200.8
  TOP w6: U4.32@2872.43,2734.88 2899,2734.88 2910.8,2723.08 2910.8,2694 2941.8,2663 v1(2941.8,2658)
  BOTTOM w6: R45.1@2899.68,2720 2900,2720 2925,2695 2925,2674.8 v1(2941.8,2658)
N16605856: C35.1 J6.1 | length 206.9
  BOTTOM w15: C35.1@2970.32,2895 2970.32,3024.26 J6.1@3025.2,3079.14
N16606070: J6.12 R40.1 | length 187.7
  BOTTOM w15: R40.1@2906.5,3479.37 2945,3479.37 2960.83,3495.2 J6.12@2960.83,3622.06
N16606404: L4.1 U4.30
N16606548: R25.1 U4.39 | length 116.4
  TOP w6: U4.39@2872.43,2845.12 2899.12,2845.12 2931.8,2877.8 v1(2931.8,2878.43)
  BOTTOM w6: R25.1@2898.68,2855 2922.11,2878.43 v1(2931.8,2878.43)
N16607242: R23.2 U4.25 | length 127.6
  TOP w6.8: R23.2@2717.62,2584.05 2766.13,2632.56 U4.25@2766.13,2691.57
N16607246: R24.2 U4.24 | length 146.7
  TOP w6.8: R24.2@2677.62,2584.05 2700.57,2607 2716,2607 2750.38,2641.38 U4.24@2750.38,2691.57
N16607250: R26.2 U4.23 | length 167.9
  TOP w6.8: R26.2@2637.62,2584.05 2676.57,2623 2711,2623 2734.63,2646.63 U4.23@2734.63,2691.57
N16607260: R27.2 U4.22 | length 189
  TOP w6.8: R27.2@2597.62,2584.05 2652.57,2639 2706,2639 2718.88,2651.88 U4.22@2718.88,2691.57
N16607264: R28.2 U4.27 | length 107.5
  TOP w6.8: R28.2@2797.62,2584.05 U4.27@2797.62,2691.57
N16607268: R29.2 U4.26 | length 117.6
  TOP w6.8: R29.2@2757.62,2584.05 2781.87,2608.3 U4.26@2781.87,2691.57
N16607434: C33.1 R384.1 Y1.1 | length 96.9
  TOP w6: R384.1@3009.68,2870 C33.1@3009.68,2910 3045.75,2910 Y1.1@3060.47,2895.28
N16607930: R35.2 U4.31 | length 101.7
  TOP w6: U4.31@2872.43,2719.13 2884.8,2719.13 2896.8,2707.13 v1(2896.8,2658)
  BOTTOM w6: v1(2896.8,2658) 2899.68,2660.88 R35.2@2899.68,2680
N16608272: C34.1 R385.2 U4.36 Y1.3 | length 306.1
  TOP w6: U4.36@2872.43,2797.87 2962.45,2797.87 R385.2@2970,2790.32 3009.36,2829.68 C34.1@3010,2829.68 3025.32,2845 3107.53,2845 3119.53,2833 Y1.3@3119.53,2804.72
N16611232: C58.1 D7.2 R69.2 R70.2 U3.12 | length 445.5
  TOP w6: v1(1914,2851) 1919.88,2845.12 U3.12@1951.16,2845.12
  BOTTOM w6: D7.2@1722.95,2855 1714.68,2863.27 R69.2@1714.68,2895 1715,2894.68 R70.2@1760,2894.68 1760,2938 1772,2950 1893.01,2950 1910.22,2932.79 1910.22,2854.78 v1(1914,2851) 1918,2855 C58.1@1940.32,2855
N16611438: C57.1 J7.15 J7.16 R71.1 | length 630.8
  BOTTOM w40: J7.16@1770.67,3309.06 2009.69,3309.06 R71.1@2030,3329.37 2034.96,3334.33 C57.1@2115,3334.33 2140.27,3309.06 J7.15@2380.51,3309.06
N16611542: R74.1 U3.32 | length 229.9
  TOP w6: U3.32@2148.02,2734.88 2178,2734.88 2186.39,2726.49 2186.39,2704.61 2201,2690 2201,2660 v1(2215,2646)
  BOTTOM w6: R74.1@2174.68,2725 2200.39,2699.29 2200.39,2660.61 v1(2215,2646)
N16611608: C56.1 J7.1 | length 134.4
  BOTTOM w12: J7.1@2300.79,3079.14 2301.34,3079.69 C56.1@2435,3079.69
N16612146: L7.1 U3.30
N16612282: R53.1 U3.39 | length 116.4
  TOP w6: U3.39@2148.02,2845.12 2174.71,2845.12 2207.39,2877.8 v1(2207.39,2878.43)
  BOTTOM w6: R53.1@2174.27,2855 2183.96,2855 v1(2207.39,2878.43)
N16612988: R51.2 U3.25 | length 131.8
  TOP w6.8: R51.2@1983.21,2584.05 2041.72,2642.56 U3.25@2041.72,2691.57
N16612992: R52.2 U3.24 | length 153
  TOP w6.8: R52.2@1943.21,2584.05 1964.41,2605.25 1983.48,2605.25 2025.97,2647.74 U3.24@2025.97,2691.57
N16612996: R54.2 U3.23 | length 174.2
  TOP w6.8: R54.2@1903.21,2584.05 1939.21,2620.05 1977.35,2620.05 2010.22,2652.92 U3.23@2010.22,2691.57
N16613006: R55.2 U3.22 | length 195.4
  TOP w6.8: R55.2@1863.21,2584.05 1914.01,2634.85 1971.18,2634.85 1994.47,2658.14 U3.22@1994.47,2691.57
N16613010: R56.2 U3.27 | length 111.7
  TOP w6.8: R56.2@2063.21,2584.05 2073.21,2594.05 U3.27@2073.21,2691.57
N16613014: R57.2 U3.26 | length 121.7
  TOP w6.8: R57.2@2023.21,2584.05 2057.46,2618.3 U3.26@2057.46,2691.57
N16613204: C54.1 R387.1 Y2.1 | length 96.9
  TOP w6: R387.1@2309.68,2870 C54.1@2309.68,2910 2345.75,2910 Y2.1@2360.47,2895.28
N16613212: C55.1 R386.2 U3.36 Y2.3 | length 330.5
  TOP w6: U3.36@2148.02,2797.87 2262.45,2797.87 R386.2@2270,2790.32 2270.64,2790.32 C55.1@2310,2829.68 2325.32,2845 2407.53,2845 2419.53,2833 Y2.3@2419.53,2804.72
N16613364: J7.11 R64.1 | length 1146
  TOP w10: J7.11@2336.42,3622.06 2336.42,3556.42 2320,3540 2240,3540 2210,3510 2210,3275 2240,3245 2300,3245 2330,3215 2415,3215 2435,3195 2435,3015.78 v1(2448.61,3002.17)
  BOTTOM w8: R64.1@2290,2886.5 2355,2886.5 2371,2902.5 2371,2965 2384,2978 2424.44,2978 v1(2448.61,3002.17)
N16613452: J7.13 R66.1 | length 129.9
  BOTTOM w15: J7.13@1914.76,3622.06 1917.45,3619.37 R66.1@2043.5,3619.37
N16613812: R63.2 U3.31 | length 112.7
  TOP w6: U3.31@2148.02,2719.13 2166.26,2719.13 2172.39,2713 2172.39,2697.81 2179,2691.2 2179,2660.5 v1(2180.5,2659)
  BOTTOM w6: R63.2@2174.68,2685 2174.68,2664.82 v1(2180.5,2659)
N16620498: R95.1 U6.3 | length 60.2
  BOTTOM w6: U6.3@674.4,3161.58 674.4,3218.09 R95.1@677,3220.69
N16620622: C86.1 R93.2 U6.4 | length 138.7
  BOTTOM w6: R93.2@600,2999.68 C86.1@675,2999.68 674.4,3000.28 U6.4@674.4,3063.16
N16621700: J8.1 J8.2 J8.3 J8.4 L12.1 | length 821.7
  TOP w20: J8.3@854.72,3712.59 887.13,3745 1162.48,3745 J8.2@1194.88,3712.59
  ART03 w20: J8.4@854.72,3533.46 J8.3@854.72,3712.59 ; J8.1@1194.88,3533.46 J8.2@1194.88,3712.59
  BOTTOM w20: J8.2@1194.88,3712.59 1201.66,3719.37 L12.1@1288.5,3719.37
N16621974: R106.1 U14.15 | length 135.7
  TOP w5.2: R106.1@5379.68,2944.37 5394.98,2959.67 5402.4,2959.67 5407.6,2954.47 5407.6,2927.48 5420.72,2914.36 5441.36,2914.36 5446.5,2909.21 U14.15@5472.32,2909.21
N16621978: R107.1 U14.14 | length 135.7
  TOP w5.2: R107.1@5379.68,2984.37 5394.98,2969.07 5406.29,2969.07 5417,2958.36 5417,2931.37 5424.61,2923.76 5441.36,2923.76 5446.5,2928.9 U14.14@5472.32,2928.9
N16622106: J10.5 J10.6 J10.11 J10.12 L13.1 | length 1174.4
  TOP w30: J10.11@5297.25,3437.01 J10.12@5812.99,3437.01
  BOTTOM w30: J10.5@5297.25,3208.66 J10.11@5297.25,3437.01 5300,3439.76 L13.1@5300,3637.87 ; J10.6@5812.99,3208.66 J10.12@5812.99,3437.01
N16622154: C104.1 C105.1 R111.1 U15.2 | length 172.4
  TOP w6: U15.2@6415,3653.15 6415,3599.05 C104.1@6395,3579.05 C105.1@6440,3579.05 R111.1@6485,3579.05
N16622302: R109.2 R110.2 U15.3 | length 127.4
  TOP w6: R110.2@6300,3579.05 R109.2@6345,3579.05 6365,3599.05 U15.3@6365,3653.15
N16622762: J9.19 J9.20 J9.21 J9.22 L11.1 | length 1215.5
  TOP w30: J9.19@4578.74,3479.57 4604.31,3454 5070.58,3454 J9.22@5096.14,3479.57
  ART03 w20: J9.20@4578.74,3255.97 J9.19@4578.74,3479.57 ; J9.21@5096.14,3255.97 J9.22@5096.14,3479.57
  BOTTOM w30: L11.1@4506.5,3679.37 4506.5,3551.81 J9.19@4578.74,3479.57
N16624042: R103.1 U13.3 | length 152.1
  BOTTOM w6: R103.1@5459.68,3619.37 5459.68,3578.29 5473.28,3564.69 5504,3564.69 5517.6,3578.29 U13.3@5517.6,3620.16
N16624166: C99.1 R102.2 U13.4 | length 149.8
  BOTTOM w6: R102.2@5459.68,3719.37 C99.1@5459.68,3669.37 5505,3669.37 5517.6,3681.97 U13.4@5517.6,3718.58
N16624284: R99.1 U7.3 | length 86.8
  BOTTOM w6: R99.1@4684.68,3649.37 4694.68,3659.37 4725,3659.37 4732.6,3651.77 U7.3@4732.6,3620.16
N16624408: C89.1 R96.2 U7.4 | length 191.7
  BOTTOM w6: R96.2@4605,3689.05 4626.52,3710.57 4663.48,3710.57 C89.1@4684.68,3689.37 4699.68,3674.37 4725.8,3674.37 4732.6,3681.17 U7.4@4732.6,3718.58
N16625162: C102.1 U14.3 Y3.1 | length 257.4
  TOP w6: U14.3@5637.68,2889.53 5724.52,2889.53 C102.1@5735,2879.05 5747.32,2891.37 5839,2891.37 5849.53,2880.84 Y3.1@5849.53,2849.09
N16625190: C103.1 U14.4 Y3.3 | length 168.2
  TOP w6: U14.4@5637.68,2909.21 5691.22,2909.21 5694.55,2905.89 5721.2,2905.89 C103.1@5735,2919.69 5754.96,2939.65 Y3.3@5790.47,2939.65
N16625358: R108.1 U14.13 | length 158
  TOP w6: R108.1@5379.68,3024.37 5425,3024.37 5435,3014.37 5435,2956.37 5442.79,2948.58 U14.13@5472.32,2948.58
N16625468: C98.1 R101.1 U14.17 | length 144
  TOP w6: R101.1@5379.68,2854.37 5395.15,2869.84 U14.17@5472.32,2869.84
  TOP w6.8: C98.1@5379.68,2809.37 R101.1@5379.68,2854.37
N16625496: R105.1 U14.16 | length 96.7
  TOP w6: R105.1@5379.68,2899.37 5389.52,2889.53 U14.16@5472.32,2889.53
N16625548: R104.1 U14.18 | length 154.5
  TOP w6: R104.1@5379.68,2764.37 5407,2791.69 5407,2836.56 5420.6,2850.16 U14.18@5472.32,2850.16
N16630017: R121.2 U16.26 | length 143
  TOP w6: R121.2@725,2895.32 750.32,2870 760,2870 787.28,2842.72 U16.26@787.28,2783.74
N16630071: C106.1 C107.1 R112.1 U16.17 | length 104.7
  TOP w6: U16.17@883.74,2687.28 931.23,2687.28 v1(948.94,2669.57)
  BOTTOM w12: v1(948.94,2669.57) 955.32,2663.19 C106.1@955.32,2640
N16630361: C112.1 U16.24 | length 134.9
  TOP w6: C112.1@765,2894.69 822.72,2836.97 U16.24@822.72,2783.74
N16630365: C113.1 U16.23 | length 125.6
  TOP w6: C113.1@805,2894.69 840.43,2859.26 U16.23@840.43,2783.74
N16630441: C115.1 U16.22 | length 116.4
  TOP w6: C115.1@845,2894.69 858.15,2881.54 U16.22@858.15,2783.74
N16630445: C117.1 U16.21 | length 137.1
  TOP w6: U16.21@883.74,2758.15 883.74,2893.43 C117.1@885,2894.69
N16630545: C118.1 U16.20 | length 164.3
  TOP w6: U16.20@883.74,2740.43 931.23,2740.43 v1(948.94,2722.72)
  BOTTOM w6: C118.1@874.68,2765 895.68,2744 927.66,2744 v1(948.94,2722.72)
N16630549: C119.1 U16.19 | length 61.2
  TOP w6: U16.19@883.74,2722.72 v1(909.57,2722.72)
  BOTTOM w6: C119.1@875,2724.68 907.61,2724.68 v1(909.57,2722.72)
N16630553: C120.1 U16.10 | length 137.4
  TOP w6: v1(734.37,2569.17) 755.2,2590 780,2590 787.28,2597.28 U16.10@787.28,2626.26
  BOTTOM w6: v1(734.37,2569.17) 765,2599.8 C120.1@765,2600.32
N16778766: Q10.1 Q11.1 Q12.1 Q13.1 R169.2 R171.1 | length 1001.8
  BOTTOM w6: Q10.1@3793.5,2602.5 3929.13,2466.87 Q13.1@4133.5,2466.87 ; Q12.1@3973.5,2601.87 Q11.1@4133.5,2601.87 4169.5,2601.87 4184,2587.37 4184,2517.37 Q13.1@4133.5,2466.87 ; R169.2@4119.68,2294.37 R171.1@4119.68,2334.37 4168.3,2334.37 4183,2349.07 4183,2416.37 4133.5,2465.87 Q13.1@4133.5,2466.87
N16778768: Q12.3 R165.2 R166.2 | length 317.6
  BOTTOM w6: R165.2@3655,2755.32 R166.2@3695,2755.32 3885.95,2564.37 Q12.3@3893.5,2564.37
N16778770: Q13.3 R167.2 R168.2 | length 689.9
  BOTTOM w6: R167.2@3565,2755.32 R168.2@3605,2755.32 3605,2722 3619,2708 3707,2708 3760,2655 3760,2575 3770,2565 3810,2565 3945.63,2429.37 Q13.3@4053.5,2429.37
N16778784: J16.G1 J16.G2 J16.G3 J16.G4 R156.1 | length 1664.6
  ART03 w20: J16.G3@3505.35,3118.66 J16.G4@3505.35,3473.01
  ART04 w20: J16.G1@3249.44,2996.62 J16.G2@3249.44,3370.64
  PWR05 w20: J16.G1@3249.44,2996.62 3249.44,2895 3289.44,2855 3464,2855 3504,2895 3504,2932.95 3533.64,2962.59 3533.64,3050.36 3505.35,3078.65 J16.G3@3505.35,3118.66
  BOTTOM w6.8: R156.1@3249.44,3669.13 R156.1@3250,3669.69
  BOTTOM w20: J16.G2@3249.44,3370.64 R156.1@3249.44,3669.13
N16779726: Q8.1 Q9.3 R158.2 | length 307.6
  BOTTOM w6: Q9.3@3453.5,2440 3553,2440 3564.5,2451.5 3564.5,2465.5 3576.5,2477.5 Q8.1@3678.5,2477.5 3712.18,2477.5 R158.2@3730,2459.68
N16779736: Q9.1 R159.1 R160.1 | length 451.8
  BOTTOM w6: R159.1@3380,2755.32 3363,2738.32 3363,2557 3377.34,2542.66 3377.34,2487.34 R160.1@3400,2464.68 3412.82,2477.5 Q9.1@3533.5,2477.5
N16779830: Q10.3 R161.2 R162.2 | length 410.4
  BOTTOM w6: R161.2@3475,2755.32 R162.2@3515,2755.32 3515,2703 3531,2687 3698,2687 3713.5,2671.5 Q10.3@3713.5,2565
N16779838: Q11.3 R163.2 R164.2 | length 427.9
  BOTTOM w6: R163.2@3740,2755.32 R164.2@3780,2755.32 3780,2695 3862.63,2612.37 3912,2612.37 3960,2564.37 Q11.3@4053.5,2564.37
N16779929: C142.1 Q7.1 R153.2 | length 94.3
  BOTTOM w6: Q7.1@3533.5,2602.5 3551.32,2584.68 C142.1@3580,2584.68 3580.32,2585 R153.2@3620.32,2585
N16781420: Q19.1 Q20.1 Q21.1 Q22.1 R190.2 R192.1 | length 546.8
  BOTTOM w6: Q20.1@4363.5,2781.87 Q21.1@4508.5,2781.87 Q22.1@4648.5,2781.87 Q19.1@4793.5,2781.87 4852.18,2781.87 R192.1@4865,2769.05
  BOTTOM w6.8: R192.1@4865,2769.05 R190.2@4905,2769.05
N16781422: Q21.3 R186.2 R187.2 | length 425.2
  BOTTOM w6: R186.2@4095,2755.32 4134.37,2755.32 R187.2@4135,2754.69 4194.69,2695 4222,2695 4239,2678 4417,2678 4428.5,2689.5 Q21.3@4428.5,2744.37
N16781424: Q22.3 R188.2 R189.2 | length 697.9
  BOTTOM w6: R188.2@4005,2755.32 R189.2@4045,2755.32 4045,2715 4057.63,2702.37 4128,2702.37 4152,2678.37 4205.63,2678.37 4222,2662 4551,2662 4568.5,2679.5 Q22.3@4568.5,2744.37
N16781438: J17.G1 J17.G2 J17.G3 J17.G4 R177.1 | length 1727.8
  ART03 w20: J17.G1@3674.64,2996.62 J17.G2@3674.64,3370.64 ; J17.G3@3930.55,3118.66 J17.G4@3930.55,3473.01
  PWR05 w20: J17.G1@3674.64,2996.62 3674.64,2851.36 3702,2824 3904,2824 3941,2861 3941,3036 3930.55,3046.45 J17.G3@3930.55,3118.66
  BOTTOM w6.8: J17.G2@3674.64,3370.64 J17.G2@3675,3371
  BOTTOM w20: J17.G2@3675,3371 R177.1@3675,3669.69
N16782370: Q17.1 Q18.3 R179.2 | length 290.4
  BOTTOM w6: R179.2@4515,2309.05 4534.68,2289.37 Q18.3@4568.5,2289.37 4608,2289.37 4620,2301.37 4620,2433.37 Q17.1@4648.5,2461.87
N16782390: Q18.1 R180.1 R181.1 | length 1610.9
  ART04 w6: v1(3815,2720) 4080,2720 4092,2708 4092,2470 4104,2458 4312,2458 4324,2470 4324,2554 4336,2566 4593,2566 4605,2554 4605,2322 4617.95,2309.05 v1(4718,2309.05)
  BOTTOM w6: v1(3815,2720) 3824,2720 3830,2726 R180.1@3830,2755.32 ; Q18.1@4648.5,2326.87 4677.18,2326.87 R181.1@4695,2309.05 v1(4718,2309.05)
N16782474: Q19.3 R182.2 R183.2 | length 938.1
  BOTTOM w6: R182.2@3920,2755.32 R183.2@3960,2755.32 3960,2714.37 3988,2686.37 4118,2686.37 4140.8,2663.57 4197.43,2663.57 4214,2647 4598,2647 4612,2661 4612,2721.37 4635,2744.37 Q19.3@4713.5,2744.37
N16782482: Q20.3 R184.2 R185.2 | length 103
  BOTTOM w6: R184.2@4185,2755.32 R185.2@4225,2755.32 4235.95,2744.37 Q20.3@4283.5,2744.37
N16782583: C154.1 Q16.1 R174.2 | length 94.1
  BOTTOM w6: Q16.1@4648.5,2601.87 4666.32,2584.05 C154.1@4695,2584.05 4734.36,2584.05 R174.2@4735,2584.69
N16783799: J18.G1 J18.G2 J18.G3 J18.G4 R195.1 | length 1426.2
  ART03 w20: J18.G1@4099.84,2996.62 J18.G2@4099.84,3370.64 ; J18.G3@4355.75,3118.66 J18.G4@4355.75,3473.01
  BOTTOM w20: J18.G2@4099.84,3370.64 4099.84,3626.84 4122.69,3649.69 R195.1@4355,3649.69 4355.75,3648.94 J18.G4@4355.75,3473.01
N16783872: D40.1 R197.1 R200.1 | length 40
  TOP w6.8: R197.1@4980.32,2754.37 R200.1@4980.32,2794.37
N16786078: D46.1 R209.1 | length 66.2
  TOP w15: R209.1@5075,2754.69 5113.39,2754.69 D46.1@5133.07,2774.37
N16791174: Q28.1 R211.1 R212.2 | length 125.9
  BOTTOM w6: R211.1@5110,2954.69 5184.32,2954.69 Q28.1@5192.5,2962.87
  BOTTOM w6.8: R212.2@5070,2954.69 R211.1@5110,2954.69
N16794123: Q27.1 R213.2 R215.1 | length 153.9
  TOP w6: v1(5249.68,3059.37) R213.2@5249.68,3029.37 5267.5,3011.55 Q27.1@5267.5,2962.87
  BOTTOM w6: R215.1@5249.68,3009.37 v1(5249.68,3059.37)
N16794280: Q27.3 R214.1 | length 101.6
  TOP w6: Q27.3@5230,2882.87 5266.5,2882.87 5274.63,2874.74 v1(5274.63,2854.37)
  BOTTOM w6: R214.1@5249.68,2834.37 5269.68,2854.37 v1(5274.63,2854.37)
N16795019: C316.1 Q29.1 R193.2 R194.1 | length 292.6
  TOP w6: R194.1@4705,2794.05 R193.2@4745,2794.05 4745,2892.37 4732.6,2904.77 4732.6,2952.97 Q29.1@4742.5,2962.87 4742.5,3012.18 C316.1@4724.68,3030
N16796110: Q28.3 R215.2 | length 134.7
  BOTTOM w6: R215.2@5210.32,3009.37 5230,2989.69 Q28.3@5230,2882.87
N16803397: C156.1 U25.6
N16803401: C156.2 L16.1 U25.2
N16803409: C157.1 R218.1 R227.1 U25.4 | length 271.1
  TOP w6.8: U25.4@6052.24,2417.6 v1(6085.4,2417.6)
  BOTTOM w6: C157.1@6024.68,2575 R218.1@6024.68,2535 R227.1@6024.68,2495 6093,2495 6104,2484 6104,2436.2 v1(6085.4,2417.6)
N16803499: R221.1 R222.1 U25.5 | length 133.9
  TOP w6.8: U25.5@6052.24,2455 v1(6085.4,2455)
  BOTTOM w6: R222.1@6024.68,2415 R221.1@6024.68,2455 v1(6085.4,2455)
N16803635: C164.1 U26.5 Y4.1 | length 314.2
  TOP w6: U26.5@4493.11,1552.2 4577.48,1552.2 C164.1@4590.32,1539.37 4615.95,1565 4660,1565 4675,1580 4730,1580 4764.53,1545.47 Y4.1@4764.53,1539.09
N16803642: R234.1 U26.10 | length 97.5
  TOP w6: U26.10@4493.11,1680.16 4589.53,1680.16 R234.1@4590.32,1679.37
N16803673: C166.1 C167.1 R235.2 U26.15 | length 160.4
  TOP w6: U26.15@4256.89,1577.8 v1(4307.8,1577.8)
  BOTTOM w6: C166.1@4240,1534.68 C167.1@4280,1534.68 R235.2@4280,1575.32 4305.32,1575.32 v1(4307.8,1577.8)
N16803735: R216.1 U26.20 | length 208.2
  TOP w4.5: R216.1@4059.68,1439.37 4078.2,1457.89 4213.39,1457.89 4221.43,1449.84 U26.20@4256.89,1449.84
N16803772: R217.1 U26.19 | length 205.5
  TOP w4.5: R217.1@4059.68,1479.37 4071.66,1467.39 4213.39,1467.39 4221.43,1475.43 U26.19@4256.89,1475.43
N16803867: R228.1 U26.18 | length 217.4
  TOP w4.5: R228.1@4059.68,1519.37 4077.41,1519.37 4092.66,1534.62 4152.94,1534.62 4178.49,1509.07 4213.39,1509.07 4221.43,1501.02 U26.18@4256.89,1501.02
N16803869: R229.1 U26.17 | length 217.4
  TOP w4.5: R229.1@4059.68,1559.37 4077.41,1559.37 4092.66,1544.12 4156.88,1544.12 4182.43,1518.57 4213.39,1518.57 4221.43,1526.61 U26.17@4256.89,1526.61
N16803965: C165.1 R230.1 Y4.3 | length 115.9
  TOP w6: R230.1@4629.68,1589.37 C165.1@4629.68,1629.37 4705.2,1629.37 Y4.3@4705.47,1629.65
N16804075: R230.2 U26.6 | length 102
  TOP w6: U26.6@4493.11,1577.8 4578.74,1577.8 R230.2@4590.32,1589.37
N16804652: J19.38 R237.1 | length 123.8
  TOP w6: R237.1@6340,3004.68 6340.24,3004.92 J19.38@6340.24,3128.35
N16804754: J19.10 R236.1 | length 123.8
  TOP w6.8: J19.10@6064.65,3128.35 6065,3128 R236.1@6065,3004.68
N16810459: R238.1 U26.14 | length 205.5
  TOP w4.5: R238.1@4059.68,1599.37 4071.74,1611.43 4213.39,1611.43 4221.43,1603.39 U26.14@4256.89,1603.39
